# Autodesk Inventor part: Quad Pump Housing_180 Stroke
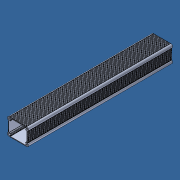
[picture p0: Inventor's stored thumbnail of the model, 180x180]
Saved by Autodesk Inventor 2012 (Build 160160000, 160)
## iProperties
Created: 2013-10
Part Number: Quad Pump Housing_180 Stroke
Material: Default
Document SubType Name: Modeling
Designer: Admin
Density: 1 g/cm^3
Author: Admin
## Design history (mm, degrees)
node "Quad Pump Housing_180 Stroke1"
node "Base1"
body "Solid1"
